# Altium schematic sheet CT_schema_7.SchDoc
size 254 x 245 mm
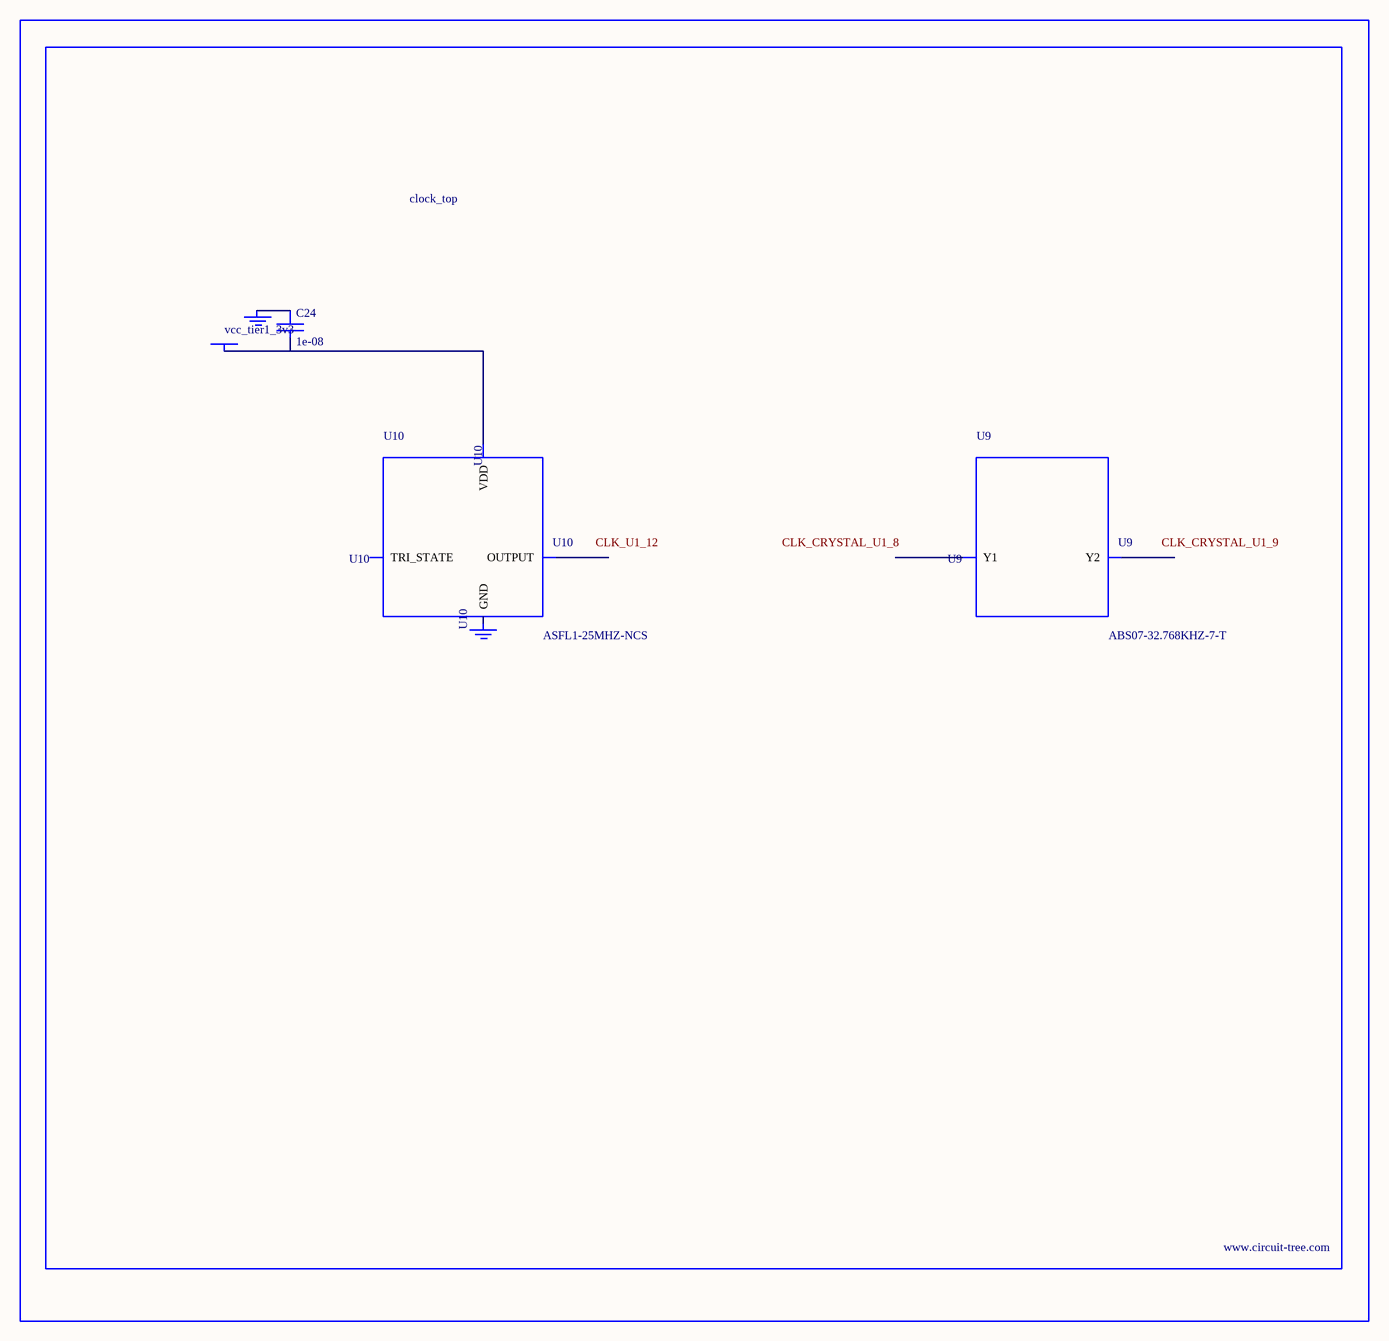
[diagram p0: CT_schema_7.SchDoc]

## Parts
BORDER6  (no value)
C24  1e-08  [C0402]
GND_INSTANCE_6_0  (no value)
GND_INSTANCE_6_1  (no value)
POWER_INSTANCE_6_0  vcc_tier1_3v3
U9  ABS07-32.768KHZ-7-T  [ABS07-32.768KHZ-7-T]
U10  ASFL1-25MHZ-NCS  [ASFL1]

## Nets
NetC24_1: C24.1 GND_INSTANCE_6_0.0(GND)
NetC24_2: C24.2 POWER_INSTANCE_6_0.0(PWR) U10.4(VDD)

Not connected (* = marked no-connect by the designer): GND_INSTANCE_6_1 0(GND); U9 1(Y1) 2(Y2); U10 1(TRI_STATE) 2(GND) 3(OUTPUT)

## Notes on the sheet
- Labels drawn without touching a wire or pin: CLK_CRYSTAL_U1_8, CLK_CRYSTAL_U1_9, CLK_U1_12

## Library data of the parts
BORDER6 = BORDER_PAGE6
C24 = C0402C103K3RAC
GND_INSTANCE_6_0 GND_INSTANCE_6_1 = GND
POWER_INSTANCE_6_0 = PWR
